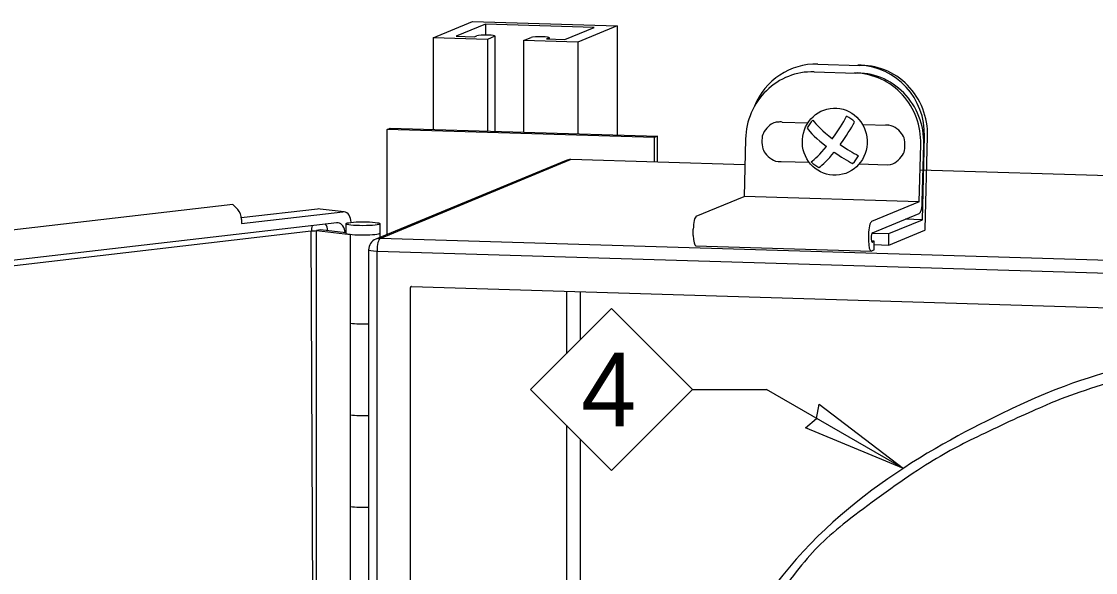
# Model space of a CAD drawing. Extents: x 99862 to 104211, y 98939 to 102076.
# Drawn here: x 102241.1 to 102473.8, y 101168.9 to 101288.4 of the extents above; entities that cross this region are included whole.
import ezdxf

# ---------------------------------------------------------------- set-up
doc = ezdxf.new("R2010")
doc.units = 0
for name, color, linetype in [('Level 1', 7, 'Continuous'), ('Level 11', 7, 'Continuous'), ('Level 12', 7, 'Continuous'), ('Level 15', 7, 'Continuous'), ('Level 17', 7, 'Continuous'), ('Level 18', 7, 'Continuous'), ('Level 20', 7, 'Continuous'), ('Level 23', 7, 'Continuous'), ('Level 3', 7, 'Continuous'), ('Level 30', 7, 'Continuous'), ('Level 6', 7, 'Continuous'), ('Level 9', 7, 'Continuous')]:
    doc.layers.add(name, color=color, linetype=linetype)

msp = doc.modelspace()

# ---------------------------------------------------------------- linework, layer by layer
at = {"layer": 'Level 1'}
for p, q in [((102359.05, 101258.25), (102317.81, 101241.19)), ((102318.77, 101241.36), (102360, 101258.43)), ((102397.79, 101257.29), (102360.08, 101258.44)), ((102483.78, 101254.68), (102435.76, 101256.14)), ((102661.4, 101230.93), (102318.77, 101241.36)), ((102316.27, 101238.88), (102316.27, 100820.74)), ((102318.11, 101238.61), (102660.74, 101228.18)), ((102318.11, 100820.94), (102318.11, 101238.61)), ((102325.35, 100821.83), (102325.35, 101230.69)), ((102325.59, 101230.93), (102653.5, 101220.95)), ((102359.12, 101229.91), (102359.12, 101216.33)), ((102362.18, 101219.39), (102362.18, 101229.81)), ((102359.12, 101200.85), (102359.12, 101059.96)), ((102362.18, 101062.49), (102362.18, 101197.78))]:
    msp.add_line(p, q, dxfattribs=at)
for centre, start, end in [((102360, 101255.94), 88.2563, 112.4791), ((102318.77, 101238.88), 112.4791, 180)]:
    msp.add_arc(centre, 2.5, start, end, dxfattribs=at)
for centre, major_axis, ratio, start_param, end_param in [((102360, 101255.94), (-0.08, -2.5), 0.260126, 3.141593, 3.258092), ((102318.77, 101238.88), (0.96, -2.31), 0.959029, 2.734261, 3.141593), ((102318.77, 101238.88), (0.08, 2.5), 0.260126, 0.1165, 1.687296), ((102318.77, 101238.88), (-2.5, 0), 0.112235, 0, 1.30593), ((102325.59, 101230.68), (0.096, -0.231), 0.959029, 3.141593, 4.305057), ((102325.59, 101230.68), (0.096, -0.231), 0.959029, 2.734261, 3.141593)]:
    msp.add_ellipse(centre, major_axis=major_axis, ratio=ratio, start_param=start_param, end_param=end_param, dxfattribs=at)
at = {"layer": 'Level 11'}
msp.add_ellipse((102417.26, 101262.31), major_axis=(0.3, -7.27), ratio=0.965403, dxfattribs=at)
for centre, major_axis, ratio, start_param, end_param in [((102415.93, 101264), (4.51, 6.19), 0.165581, 4.664043, 5.491937), ((102416.82, 101262.29), (6.47, 0.27), 0.965403, 0.715535, 1.047495), ((102416.84, 101262.29), (0.27, -6.47), 0.965403, 3.859694, 4.191654), ((102418.56, 101263.18), (6.19, -4.51), 0.165581, 3.52142, 4.536345), ((102417.64, 101262.76), (-4.5, -6.19), 0.165581, 1.520706, 2.350146), ((102417.32, 101261.48), (-6.19, 4.5), 0.165581, 0.380026, 1.385852), ((102415.93, 101264), (4.51, 6.19), 0.165581, 3.52142, 4.383143), ((102418.56, 101263.18), (6.19, -4.51), 0.165581, 4.812672, 5.491937), ((102417.64, 101262.76), (-4.5, -6.19), 0.165581, 0.380026, 1.239194), ((102417.32, 101261.48), (-6.19, 4.5), 0.165581, 1.662256, 2.350146), ((102416.84, 101262.29), (0.27, -6.47), 0.965403, 0.715535, 1.047495), ((102416.82, 101262.29), (6.47, 0.27), 0.965403, 3.859694, 4.191654)]:
    msp.add_ellipse(centre, major_axis=major_axis, ratio=ratio, start_param=start_param, end_param=end_param, dxfattribs=at)
at = {"layer": 'Level 12'}
for p, q in [((102305.87, 101243.18), (102305, 101243.09)), ((102305, 101243.09), (102312.38, 101242.23)), ((102305, 100819.97), (102305, 101243.09)), ((102311.34, 101242.54), (102305.87, 101243.18)), ((102312.38, 101222.96), (102312.38, 101242.23)), ((102318.79, 101241.59), (102318.79, 101242.52)), ((102312.38, 101203.09), (102312.38, 101222.96)), ((102312.38, 101183.22), (102312.38, 101203.09)), ((102312.38, 101163.34), (102312.38, 101183.22))]:
    msp.add_line(p, q, dxfattribs=at)
for centre, major_axis, start_param, end_param in [((102315.06, 101242.52), (-3.72, 0), 6.22656, 6.283185), ((102315.06, 101242.52), (-3.72, 0), 6.283185, 7.051772), ((102315.06, 101242.52), (3.72, 0), 3.141593, 6.018319), ((102315.06, 101242.52), (-3.72, 0), 2.876726, 3.141593), ((102315.06, 101223.25), (3.72, 0), 3.910179, 5.042102), ((102315.06, 101203.38), (-3.72, 0), 0.768587, 1.900509), ((102315.06, 101183.51), (3.72, 0), 3.910179, 5.042102)]:
    msp.add_ellipse(centre, major_axis=major_axis, ratio=0.112235, start_param=start_param, end_param=end_param, dxfattribs=at)
at = {"layer": 'Level 15'}
for p in [(102386.48, 101208.59), (102432.17, 101191.45)]:
    msp.add_line(p, (102402.48, 101208.59), dxfattribs=at)
msp.add_lwpolyline([(102432.17, 101191.45), (102410.91, 101200.28), (102413.32, 101202.33), (102413.89, 101205.45)], close=True, dxfattribs=at)
at = {"layer": 'Level 17'}
for p, q in [((102330.25, 101284.85), (102338.76, 101288.37)), ((102341.62, 101287.81), (102335.24, 101285.17)), ((102338.76, 101288.37), (102370.13, 101287.41)), ((102341.62, 101287.81), (102341.62, 101285.44)), ((102365.14, 101287.09), (102341.62, 101287.81)), ((102358.76, 101284.45), (102365.14, 101287.09)), ((102370.13, 101287.41), (102361.62, 101283.89)), ((102370.13, 101287.41), (102370.13, 101263.76)), ((102330.25, 101284.85), (102330.25, 101264.97)), ((102342.02, 101284.49), (102330.25, 101284.85)), ((102335.24, 101285.17), (102339.16, 101285.05)), ((102339.16, 101285.05), (102339.7, 101285.27)), ((102343.62, 101285.15), (102342.02, 101284.49)), ((102342.02, 101284.49), (102342.02, 101264.62)), ((102343.69, 101264.57), (102343.69, 101285.21)), ((102349.86, 101284.25), (102351.46, 101284.91)), ((102349.86, 101284.25), (102349.86, 101264.38)), ((102361.62, 101283.89), (102349.86, 101284.25)), ((102355.38, 101284.79), (102354.84, 101284.57)), ((102354.84, 101284.57), (102358.76, 101284.45)), ((102355.45, 101284.55), (102355.45, 101284.85)), ((102361.62, 101283.89), (102361.62, 101264.02))]:
    msp.add_line(p, q, dxfattribs=at)
for centre, start_param, end_param in [((102341.64, 101285.21), 1.30593, 2.876726), ((102341.67, 101285.21), 0, 1.30593), ((102341.67, 101285.21), 6.018319, 6.283185), ((102353.4, 101284.85), 1.30593, 2.876726), ((102353.43, 101284.85), 6.283185, 7.589115), ((102353.43, 101284.85), 6.018319, 6.283185)]:
    msp.add_ellipse(centre, major_axis=(2.01, 0), ratio=0.112235, start_param=start_param, end_param=end_param, dxfattribs=at)
at = {"layer": 'Level 18'}
for p, q in [((102378.85, 101263.49), (102378.2, 101263.22)), ((102378.85, 101257.85), (102378.85, 101263.49))]:
    msp.add_line(p, q, dxfattribs=at)
for points in [[(102320.29, 101242.22), (102320.29, 101264.99), (102320.94, 101265.26), (102378.85, 101263.49)], [(102378.2, 101257.87), (102378.2, 101263.22), (102320.29, 101264.99)]]:
    msp.add_lwpolyline(points, dxfattribs=at)
at = {"layer": 'Level 20'}
msp.add_lwpolyline([(102368.93, 101226.14), (102386.48, 101208.59), (102368.93, 101191.04), (102351.38, 101208.59)], close=True, dxfattribs=at)
at = {"layer": 'Level 23'}
for p, q in [((102311.34, 101244.53), (102311.34, 101242.52)), ((102318.79, 101241.59), (102318.79, 101244.53))]:
    msp.add_line(p, q, dxfattribs=at)
msp.add_ellipse((102315.06, 101244.53), major_axis=(-3.72, 0), ratio=0.112235, dxfattribs=at)
at = {"layer": 'Level 3'}
for p, q in [((102286.89, 101248.73), (102063.28, 101222.66)), ((102286.89, 101248.73), (102287.94, 101247.61)), ((102305.19, 101247.72), (102288.7, 101245.79)), ((102288.72, 101244.55), (102310.67, 101247.11)), ((102310.97, 101247.11), (102305.77, 101247.72)), ((102309.36, 101244.74), (102051.67, 101214.7)), ((102288.72, 101245.45), (102288.72, 101244.55)), ((102303.87, 101242.9), (102050.13, 101213.32)), ((102305, 100991.25), (102303.87, 101242.9))]:
    msp.add_line(p, q, dxfattribs=at)
msp.add_arc((102305.48, 101245.23), 2.5, 83.3479, 96.6486, dxfattribs=at)
for centre, major_axis, ratio, start_param, end_param in [((102286.99, 101245.66), (-0.29, 2.48), 0.688289, 4.551089, 5.533296), ((102310.68, 101244.63), (0.29, 2.48), 0.71602, 0, 0.167679), ((102310.68, 101244.63), (0.29, 2.48), 0.71602, 4.88008, 6.283185), ((102309.37, 101242.26), (-0.29, -2.48), 0.71602, 3.141593, 3.309272), ((102309.37, 101242.26), (-0.29, -2.48), 0.71602, 1.778647, 3.141593), ((102305.6, 101242.69), (-0.29, 2.48), 0.688289, 0.879041, 1.409497), ((102305.6, 101242.69), (2.5, 0.01), 0.116506, 1.812003, 2.33645), ((102305.6, 101242.69), (-0.29, -2.48), 0.71602, 1.777802, 2.441174)]:
    msp.add_ellipse(centre, major_axis=major_axis, ratio=ratio, start_param=start_param, end_param=end_param, dxfattribs=at)
at = {"layer": 'Level 30'}
for points in [[(102492.15, 101215.46), (102490.81, 101215.29), (102482.9, 101214.1), (102460.41, 101208.52), (102393.4, 101170.91), (102377.25, 101084.36), (102372.86, 101072.92), (102370.82, 101069.79), (102370.54, 101069.4)], [(102492.38, 101213.47), (102491.09, 101213.31), (102489.67, 101213.1), (102484.6, 101212.21), (102480.39, 101211.29), (102469.68, 101207.9), (102463.18, 101205.42), (102447.09, 101197.96), (102437.56, 101193), (102419.16, 101179.88), (102410.3, 101171.73), (102400.16, 101156.6), (102397.28, 101151.02), (102392.33, 101139.44), (102390.27, 101133.43), (102386.76, 101121.61), (102385.31, 101115.8), (102382.84, 101104.99), (102381.81, 101099.99), (102379.02, 101087.14), (102377.57, 101081.49), (102375.73, 101075.59), (102375.17, 101074.04), (102374.11, 101071.5), (102373.6, 101070.51), (102372.66, 101068.93), (102372.22, 101068.27), (102371.74, 101067.68)]]:
    msp.add_open_spline(points, degree=3, dxfattribs=at)
at = {"layer": 'Level 6'}
for p, q in [((102413.59, 101279.12), (102422.61, 101278.84)), ((102436.24, 101245.39), (102436.7, 101263.41)), ((102436.84, 101243.38), (102437.35, 101263.44)), ((102428.98, 101242.39), (102436.24, 101245.39)), ((102436.24, 101245.39), (102432.5, 101245.51)), ((102425.33, 101242.5), (102428.98, 101242.39)), ((102428.98, 101239.9), (102436.78, 101243.13)), ((102428.98, 101239.9), (102428.98, 101242.39)), ((102425.81, 101240), (102428.98, 101239.9))]:
    msp.add_line(p, q, dxfattribs=at)
for centre, major_axis, ratio, start_param, end_param in [((102413.21, 101264.12), (0.63, -14.99), 0.965403, 3.07178, 4.270302), ((102422.88, 101263.88), (0.63, -14.99), 0.965403, 1.500987, 3.141593), ((102422.22, 101263.85), (0.63, -14.99), 0.965403, 1.500987, 3.071783), ((102436.78, 101243.38), (0.008, 0.25), 0.260126, 3.258092, 4.731227)]:
    msp.add_ellipse(centre, major_axis=major_axis, ratio=ratio, start_param=start_param, end_param=end_param, dxfattribs=at)
at = {"layer": 'Level 9'}
for p, q in [((102412.79, 101277.45), (102421.81, 101277.17)), ((102405.87, 101266.57), (102411.44, 101266.4)), ((102423.29, 101266.04), (102428.82, 101265.87)), ((102397.93, 101262.89), (102397.61, 101250.42)), ((102435.58, 101249.27), (102435.9, 101261.74)), ((102436.23, 101249.29), (102436.55, 101261.77)), ((102405.68, 101258.03), (102411.72, 101257.84)), ((102422.57, 101257.51), (102428.63, 101257.33)), ((102387.27, 101246.14), (102397.61, 101250.42)), ((102435.58, 101249.27), (102397.61, 101250.42)), ((102435.58, 101249.27), (102425.24, 101244.99)), ((102425.41, 101242.57), (102435.58, 101246.78)), ((102386.62, 101242), (102386.62, 101243.39)), ((102424.58, 101242.23), (102424.58, 101240.84)), ((102425.15, 101241.46), (102425.15, 101241.47)), ((102425.81, 101240.74), (102425.24, 101240.76)), ((102425.41, 101240.57), (102425.35, 101240.57)), ((102425.81, 101240.74), (102425.41, 101240.57)), ((102425.81, 101238.87), (102425.81, 101240.74)), ((102387.09, 101239.77), (102425.24, 101238.61)), ((102425.24, 101238.63), (102425.81, 101238.87))]:
    msp.add_line(p, q, dxfattribs=at)
for centre, major_axis, ratio, start_param, end_param in [((102412.41, 101262.45), (0.63, -14.99), 0.965403, 3.071783, 4.64258), ((102422.07, 101262.21), (0.63, -14.99), 0.965403, 1.500987, 3.141593), ((102421.42, 101262.18), (0.63, -14.99), 0.965403, 1.500987, 3.071787), ((102435.58, 101249.27), (-0.08, -2.5), 0.260126, 0.1165, 1.589635), ((102387.27, 101243.66), (0.08, 2.5), 0.260126, 0.1165, 1.687296), ((102425.24, 101242.5), (-0.08, -2.5), 0.260126, 3.258092, 4.828889), ((102425.41, 101241.58), (0.03, 1), 0.260126, 0.1165, 1.687296), ((102387.27, 101242.27), (0.08, 2.5), 0.260126, 1.687296, 3.141593), ((102425.24, 101241.11), (-0.08, -2.5), 0.260126, 4.828889, 6.283185), ((102425.41, 101241.56), (0.03, 1), 0.260126, 1.687296, 3.141593), ((102425.41, 101241.56), (0.03, 1), 0.260126, 3.141593, 3.258092), ((102425.24, 101241.11), (-0.08, -2.5), 0.260126, 0, 0.1165)]:
    msp.add_ellipse(centre, major_axis=major_axis, ratio=ratio, start_param=start_param, end_param=end_param, dxfattribs=at)
for points in [[(102405.87, 101266.57), (102405.69, 101266.59), (102405.5, 101266.59), (102404.28, 101266.54), (102403.29, 101266.08), (102401.83, 101264.42), (102401.42, 101263.3), (102401.52, 101260.97), (102402.02, 101259.89), (102403.62, 101258.36), (102404.64, 101257.98), (102405.68, 101258.03)], [(102428.63, 101257.33), (102429.67, 101257.37), (102430.65, 101257.84), (102432.12, 101259.49), (102432.52, 101260.61), (102432.42, 101262.94), (102431.93, 101264.03), (102430.33, 101265.55), (102429.31, 101265.93), (102428.27, 101265.88)]]:
    msp.add_open_spline(points, degree=3, dxfattribs=at)

# ---------------------------------------------------------------- texts
at = {"layer": 'Level 20'}
msp.add_text('4', height=16, dxfattribs=at).set_placement((102362.34, 101200.59))

doc.saveas('drawing.dxf')
